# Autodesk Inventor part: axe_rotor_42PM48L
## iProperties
Created: 2011-01
Part Number: axe_rotor_42PM48L
Document SubType Name: Modeling
Designer: eric
Density: 1 g/cm^3
Mass: 0.424115 g
Surface Area: 5.79624 cm^2
Volume: 0.424115 cm^3
Author: eric
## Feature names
1. Base1
